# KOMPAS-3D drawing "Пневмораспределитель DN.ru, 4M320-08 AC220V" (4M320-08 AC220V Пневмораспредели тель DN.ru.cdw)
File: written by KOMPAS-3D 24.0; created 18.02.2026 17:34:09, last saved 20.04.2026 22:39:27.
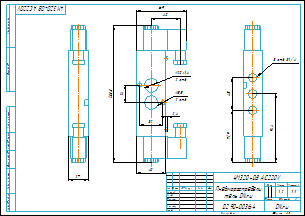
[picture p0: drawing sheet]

Document properties: Автор: R2D2; Форматы листов документа: A3; Полное имя файла: 4M320-08 AC220V Пневмораспределитель DN.RU.m3d; Масса: 1.2; Наименование: Пневмораспределитель DN.ru; Количество листов документа: 1; Примечание: D290-00364

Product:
- Part/product: Пневмораспределитель DN.ru  | designation 4M320-08 AC220V
    Масса: 1.2
    Раздел спецификации: Прочие изделия
    Форматы листов документа: A3
    Примечание: D290-00364

Views: Вид 1, Спереди, Проекционный вид 2, Проекционный вид 3
Referenced files in E:\Работа\Зайцев\Аксессуары для пневмоприводов\Пневмораспределители DN.ru\4M320 AC220V Пневмораспределитель DN.RU\4M320-08 AC220V Пневмораспределитель DN.RU\: 4M320-08 AC220V 1-4' Пневмораспределитель DN.RU.m3d, 4M320-08 AC220V Пневмораспределитель DN.RU.m3d
Referenced files in E:\Работа\Зайцев\Для компаса\: чертеж DN.ru А3.cdt
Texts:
  чертеж DN.ru А3.cdt
  Пневмораспредели
  тель DN.ru
  Пневмораспределитель DN.ru
  4M320-08 AC220V Пневмораспределитель DN.ru
Dimensions and other numbers on the sheet: 0; 3; 2; 4; 71,9; 45; 94,4; 3 отв. G1/4'; 4M320-08 AC220V; 5; 69; 40; 32; 24; 188,8; 2,4; 5,5; 2 отв.; 20; 6; 27; 1:1; 1; 1,2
